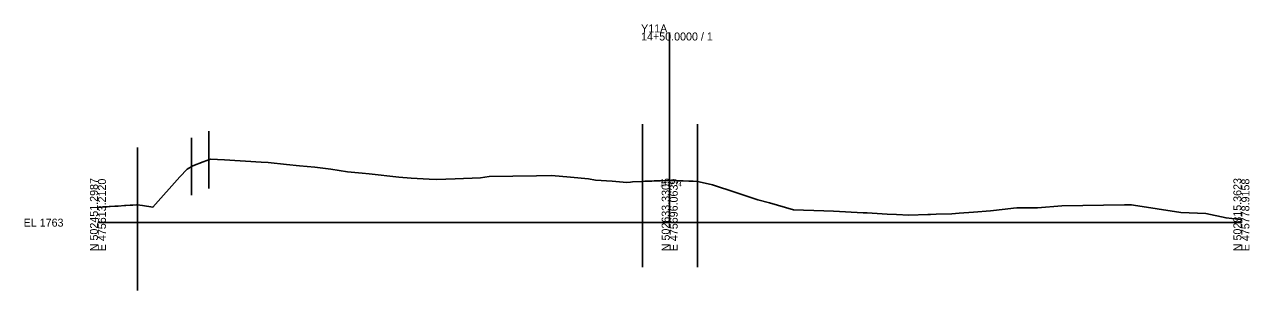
# Model space of a CAD drawing. Extents: x -26 to 403, y -10 to 5098.
# Drawn here: x -25.7 to 402.8, y 4476.3 to 4569.3 of the extents above; entities that cross this region are included whole.
import ezdxf

# ---------------------------------------------------------------- set-up
doc = ezdxf.new("R2010")
doc.units = 0
for name, color, linetype in [('Exist Cross Section Cell', 7, 'Continuous'), ('Exist XS Center Line Elevation Label', 7, 'Continuous'), ('Exist XS Ground Line', 7, 'Continuous'), ('Scratch_Level_1', 7, 'Continuous'), ('Scratch_Level_5', 7, 'Continuous')]:
    doc.layers.add(name, color=color, linetype=linetype)

msp = doc.modelspace()

# ---------------------------------------------------------------- linework, layer by layer
at = {"layer": 'Exist Cross Section Cell'}
for p, q in [((200, 4500), (200, 4566.54)), ((0, 4500), (200, 4500)), ((200, 4500), (400, 4500))]:
    msp.add_line(p, q, dxfattribs=at)
at = {"layer": 'Exist XS Ground Line'}
msp.add_lwpolyline([(0, 4505.34), (1.51, 4505.44), (2.06, 4505.48), (3.24, 4505.56), (3.96, 4505.61), (4.3, 4505.63), (5.86, 4505.73), (7.07, 4505.81), (9.28, 4505.96), (9.78, 4505.99), (11.29, 4506.1), (12.15, 4506.15), (13.47, 4506.24), (13.84, 4506.26), (14.62, 4506.13), (15.59, 4505.97), (19.25, 4505.41), (28.61, 4516.03), (31.17, 4518.77), (33.14, 4519.86), (36.86, 4521.24), (39.38, 4522.18), (44.26, 4521.95), (57.09, 4521.22), (59.52, 4521.03), (65.98, 4520.34), (70.5, 4519.87), (75.92, 4519.38), (81.49, 4518.72), (87.3, 4517.79), (92.48, 4517.26), (94.85, 4517.06), (105.22, 4515.9), (109.55, 4515.58), (115.88, 4515.27), (118.44, 4515.06), (124.93, 4515.37), (133.81, 4515.68), (136.85, 4516.12), (153.47, 4516.4), (158.71, 4516.52), (165.27, 4515.92), (171.63, 4515.33), (174.07, 4514.89), (179.87, 4514.54), (185.05, 4514.06), (186.26, 4514.18), (186.97, 4514.23), (190.52, 4514.45), (191.26, 4514.49), (191.84, 4514.51), (193.8, 4514.57), (194.63, 4514.6), (196.65, 4514.65), (199.27, 4514.72), (199.99, 4514.74), (202.44, 4514.69), (204.75, 4514.63), (206.72, 4514.56), (207.5, 4514.53), (208.21, 4514.51), (209.78, 4514.44), (210.32, 4514.32), (214.98, 4513.27), (223.2, 4510.53), (230.79, 4507.97), (234.87, 4506.91), (243.37, 4504.53), (253.92, 4504.1), (257.32, 4504.01), (267.67, 4503.49), (268.55, 4503.43), (269.07, 4503.41), (276.1, 4502.96), (279.3, 4502.8), (283.65, 4502.61), (290.29, 4502.91), (291.2, 4502.91), (293.22, 4502.98), (298.76, 4503.12), (301.28, 4503.28), (306.31, 4503.69), (312.27, 4504.18), (317.36, 4504.77), (320.31, 4505.11), (321.41, 4505.24), (326.95, 4505.15), (328.68, 4505.13), (337.15, 4505.84), (359.17, 4506.19), (360.65, 4506.21), (361.51, 4506.19), (362.26, 4506.1), (378.8, 4503.54), (387.52, 4503.22), (394.67, 4501.65), (396.63, 4501.46), (400, 4501.11)], dxfattribs=at)
at = {"layer": 'Scratch_Level_1'}
for p, q in [((190.52, 4534.45), (190.52, 4484.45)), ((209.78, 4534.44), (209.78, 4484.44)), ((13.84, 4526.26), (13.84, 4476.26))]:
    msp.add_line(p, q, dxfattribs=at)
at = {"layer": 'Scratch_Level_5'}
for p, q in [((32.77, 4529.65), (32.77, 4509.65)), ((38.8, 4531.96), (38.8, 4511.96))]:
    msp.add_line(p, q, dxfattribs=at)

# ---------------------------------------------------------------- texts
at = {"layer": 'Exist Cross Section Cell'}
for s, p in [('Y11A', (190, 4566.54)), ('14+50.0000 / 1', (190, 4563.74)), ('EL 1763', (-26, 4498.6))]:
    msp.add_text(s, height=2.8, dxfattribs=at).set_placement(p)
for s, p in [('N 502451.2987', (0, 4490)), ('E 475613.2120', (2.8, 4490)), ('N 502633.3305', (200, 4490)), ('E 475696.0639', (202.8, 4490)), ('N 502815.3623', (400, 4490)), ('E 475778.9158', (402.8, 4490))]:
    msp.add_text(s, height=2.8, rotation=90, dxfattribs=at).set_placement(p)
at = {"layer": 'Exist XS Center Line Elevation Label'}
msp.add_text('1777.74', height=1.5, dxfattribs=at).set_placement((196.73, 4512.74))

doc.saveas('drawing.dxf')
